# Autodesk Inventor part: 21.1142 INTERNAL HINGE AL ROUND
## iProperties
Created: 2007-01
Part Number: 21.1142 INTERNAL HINGE AL ROUND
Document SubType Name: Modeling
Designer: Andy Moles
Material: Aluminum-6061
Density: 2.71 g/cm^3
Author: Andy Moles
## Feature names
1. Extrusion1
2. Extrusion2
3. Extrusion3
